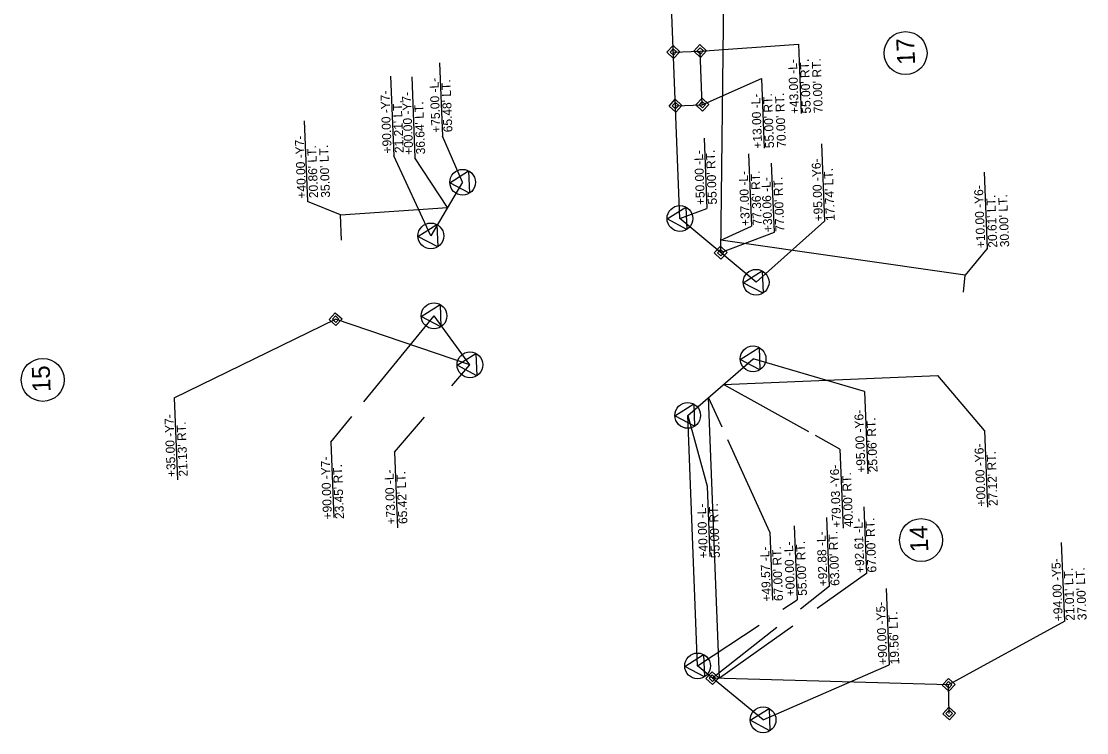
# Model space of a CAD drawing. Extents: x 1627970 to 1628801, y 761752 to 765698.
# Drawn here: x 1628129 to 1628724, y 762940 to 763337 of the extents above; entities that cross this region are included whole.
import ezdxf

# ---------------------------------------------------------------- set-up
doc = ezdxf.new("R2010")
doc.units = 0
for name, color, linetype in [('Exist Other Culture Gas Pump or Vent CELL', 7, 'Continuous'), ('Exist Property Line Leader', 7, 'Continuous'), ('Exist Property Line Text', 7, 'Continuous'), ('Exist Property Owner Number CELL', 7, 'Continuous'), ('Exist Right of Way Control of Access Line', 7, 'Continuous'), ('Exist Right of Way Monument Leader', 7, 'Continuous'), ('Exist Right of Way Monument Text', 7, 'Continuous'), ('Exist Roads EOT', 7, 'Continuous'), ('Exist Utilities Gas UG Line', 7, 'Continuous'), ('Exist Utilities Gas UG Line Text', 7, 'Continuous'), ('Exist Utilities Other Unknown UG SUE Text', 7, 'Continuous')]:
    doc.layers.add(name, color=color, linetype=linetype)

msp = doc.modelspace()

# ---------------------------------------------------------------- linework, layer by layer
at = {"layer": 'Exist Other Culture Gas Pump or Vent CELL'}
for p, q in [((1628508.24, 763320.26), (1628563.07, 763324.14)), ((1628563.07, 763324.14), (1628564.6, 763285.32)), ((1628509.42, 763290.28), (1628542.51, 763304.85)), ((1628542.51, 763304.85), (1628544.04, 763266.03))]:
    msp.add_line(p, q, dxfattribs=at)
at = {"layer": 'Exist Property Line Leader'}
for p, q in [((1628519.69, 763207.68), (1628522.83, 763457.94)), ((1628379.63, 763145.05), (1628304.6, 763170.52)), ((1628646.98, 762966.38), (1628515.04, 762970.13)), ((1628647.3, 762950.39), (1628646.98, 762966.38))]:
    msp.add_line(p, q, dxfattribs=at)
at = {"layer": 'Exist Property Line Text'}
for p, q in [((1628622.91, 763319.11), (1628622.91, 763319.11)), ((1628141.06, 763136.66), (1628141.06, 763136.66)), ((1628631.59, 763047.2), (1628631.59, 763047.2))]:
    msp.add_line(p, q, dxfattribs=at)
for centre in [(1628622.91, 763319.11), (1628141.06, 763136.66), (1628631.59, 763047.2)]:
    msp.add_circle(centre, 12, dxfattribs=at)
at = {"layer": 'Exist Property Owner Number CELL'}
for p, q in [((1628493.25, 763319.67), (1628508.24, 763320.26)), ((1628509.42, 763290.28), (1628508.24, 763320.26)), ((1628494.44, 763289.69), (1628509.42, 763290.28))]:
    msp.add_line(p, q, dxfattribs=at)
at = {"layer": 'Exist Right of Way Control of Access Line'}
for p, q in [((1628496.92, 763226.74), (1628473.87, 763811.28)), ((1628375.55, 763246.97), (1628357.79, 763217.01)), ((1628539.46, 763191.13), (1628496.92, 763226.74)), ((1628379.63, 763145.05), (1628359.56, 763172.38)), ((1628501.25, 763116.82), (1628537.76, 763148.37)), ((1628506.77, 762976.93), (1628501.25, 763116.82)), ((1628543.35, 762946.87), (1628506.77, 762976.93))]:
    msp.add_line(p, q, dxfattribs=at)
at = {"layer": 'Exist Right of Way Monument Leader'}
for points in [[(1628489.66, 763319.52), (1628493.11, 763323.26), (1628496.85, 763319.81), (1628493.4, 763316.07)], [(1628504.65, 763320.11), (1628508.1, 763323.85), (1628511.84, 763320.4), (1628508.38, 763316.66)], [(1628506.44, 763320.19), (1628508.17, 763322.06), (1628510.04, 763320.33), (1628508.31, 763318.46)], [(1628491.46, 763319.59), (1628493.18, 763321.46), (1628495.05, 763319.74), (1628493.32, 763317.87)], [(1628490.84, 763289.55), (1628494.29, 763293.29), (1628498.03, 763289.83), (1628494.58, 763286.09)], [(1628505.83, 763290.14), (1628509.28, 763293.88), (1628513.02, 763290.42), (1628509.57, 763286.68)], [(1628492.64, 763289.62), (1628494.37, 763291.49), (1628496.23, 763289.76), (1628494.51, 763287.89)], [(1628507.63, 763290.21), (1628509.35, 763292.08), (1628511.22, 763290.35), (1628509.5, 763288.48)], [(1628516.09, 763207.54), (1628519.55, 763211.27), (1628523.28, 763207.82), (1628519.83, 763204.08)], [(1628517.89, 763207.61), (1628519.62, 763209.48), (1628521.49, 763207.75), (1628519.76, 763205.88)], [(1628301, 763170.38), (1628304.45, 763174.12), (1628308.19, 763170.66), (1628304.74, 763166.92)], [(1628302.8, 763170.45), (1628304.52, 763172.32), (1628306.39, 763170.59), (1628304.67, 763168.72)], [(1628511.45, 762969.99), (1628514.9, 762973.73), (1628518.64, 762970.27), (1628515.19, 762966.54)], [(1628513.24, 762970.06), (1628514.97, 762971.93), (1628516.84, 762970.2), (1628515.11, 762968.33)], [(1628643.38, 762966.24), (1628646.84, 762969.98), (1628650.57, 762966.52), (1628647.12, 762962.78)], [(1628645.18, 762966.31), (1628646.91, 762968.18), (1628648.78, 762966.45), (1628647.05, 762964.58)], [(1628643.7, 762950.25), (1628647.16, 762953.99), (1628650.89, 762950.53), (1628647.44, 762946.8)], [(1628645.5, 762950.32), (1628647.23, 762952.19), (1628649.09, 762950.46), (1628647.37, 762948.59)]]:
    msp.add_lwpolyline(points, close=True, dxfattribs=at)
at = {"layer": 'Exist Right of Way Monument Text'}
for p, q in [((1628307.28, 763228.8), (1628367.17, 763232.83)), ((1628307.84, 763214.67), (1628307.28, 763228.8)), ((1628656.22, 763195.03), (1628519.77, 763214.63)), ((1628655.35, 763185.64), (1628656.22, 763195.03)), ((1628521.21, 763134.07), (1628640.95, 763139.09)), ((1628519.05, 762970.02), (1628512.87, 763126.86))]:
    msp.add_line(p, q, dxfattribs=at)
at = {"layer": 'Exist Roads EOT'}
for p, q in [((1628549.66, 763219.19), (1628548.09, 763257.67)), ((1628519.69, 763207.68), (1628549.66, 763219.19)), ((1628214.44, 763126.7), (1628304.6, 763170.52)), ((1628214.44, 763126.7), (1628216.26, 763080.77)), ((1628580.45, 763021.49), (1628578.88, 763059.86)), ((1628711.81, 763002), (1628710.01, 763045.88)), ((1628580.45, 763021.49), (1628564.19, 763008.72)), ((1628711.81, 763002), (1628646.98, 762966.38)), ((1628551.04, 762998.4), (1628515.04, 762970.13))]:
    msp.add_line(p, q, dxfattribs=at)
at = {"layer": 'Exist Utilities Gas UG Line'}
for p, q in [((1628362.69, 763313.63), (1628364.3, 763272.66)), ((1628335.31, 763306.19), (1628337.06, 763261.75)), ((1628375.55, 763246.97), (1628364.3, 763272.66)), ((1628510.48, 763271.57), (1628512.03, 763232.29)), ((1628576.03, 763268.36), (1628577.73, 763225.3)), ((1628357.79, 763217.01), (1628337.06, 763261.75)), ((1628496.92, 763226.74), (1628512.03, 763232.29)), ((1628539.46, 763191.13), (1628577.73, 763225.3)), ((1628320.3, 763124.33), (1628359.56, 763172.38)), ((1628369.45, 763133.28), (1628379.63, 763145.05)), ((1628599.97, 763130.08), (1628537.76, 763148.37)), ((1628599.97, 763130.08), (1628601.78, 763084.26)), ((1628301.96, 763101.88), (1628313.68, 763116.23)), ((1628337.51, 763096.3), (1628354.3, 763115.74)), ((1628501.25, 763116.82), (1628512.12, 763077.28)), ((1628301.96, 763101.88), (1628303.62, 763059.82)), ((1628337.51, 763096.3), (1628339.18, 763053.99)), ((1628512.12, 763077.28), (1628513.67, 763038)), ((1628560.69, 763055.23), (1628562.32, 763013.84)), ((1628612.13, 763020.23), (1628613.81, 762977.6)), ((1628554.47, 763008.62), (1628562.32, 763013.84)), ((1628506.77, 762976.93), (1628541.11, 762999.75)), ((1628543.35, 762946.87), (1628613.81, 762977.6))]:
    msp.add_line(p, q, dxfattribs=at)
at = {"layer": 'Exist Utilities Gas UG Line Text'}
for p, q in [((1628347.13, 763305.76), (1628348.91, 763260.62)), ((1628287.13, 763281.24), (1628288.91, 763236.19)), ((1628535.26, 763262.91), (1628536.85, 763222.49)), ((1628367.17, 763232.83), (1628348.91, 763260.62)), ((1628666.86, 763252.64), (1628668.55, 763209.91)), ((1628307.28, 763228.8), (1628288.91, 763236.19)), ((1628519.77, 763214.63), (1628536.85, 763222.49)), ((1628668.55, 763209.91), (1628656.22, 763195.03)), ((1628667.09, 763108.4), (1628640.95, 763139.09)), ((1628568.84, 763107.63), (1628521.21, 763134.07)), ((1628520.43, 763110.29), (1628512.87, 763126.86)), ((1628667.09, 763108.4), (1628668.78, 763065.67)), ((1628547.19, 763051.67), (1628523.71, 763103.1)), ((1628586.31, 763097.94), (1628572.68, 763105.5)), ((1628586.31, 763097.94), (1628588.05, 763053.87)), ((1628599.58, 763065.79), (1628601.05, 763028.51)), ((1628547.19, 763051.67), (1628548.69, 763013.66)), ((1628601.05, 763028.51), (1628573.62, 763008.95)), ((1628559.98, 762999.22), (1628519.05, 762970.02))]:
    msp.add_line(p, q, dxfattribs=at)
at = {"layer": 'Exist Utilities Other Unknown UG SUE Text'}
for p, q in [((1628493.25, 763319.67), (1628493.25, 763319.67)), ((1628508.24, 763320.26), (1628508.24, 763320.26)), ((1628494.44, 763289.69), (1628494.44, 763289.69)), ((1628509.42, 763290.28), (1628509.42, 763290.28)), ((1628375.55, 763246.97), (1628375.55, 763246.97)), ((1628496.92, 763226.74), (1628496.92, 763226.74)), ((1628357.79, 763217.01), (1628357.79, 763217.01)), ((1628519.69, 763207.68), (1628519.69, 763207.68)), ((1628539.46, 763191.13), (1628539.46, 763191.13)), ((1628304.6, 763170.52), (1628304.6, 763170.52)), ((1628359.56, 763172.38), (1628359.56, 763172.38)), ((1628379.63, 763145.05), (1628379.63, 763145.05)), ((1628537.76, 763148.37), (1628537.76, 763148.37)), ((1628501.25, 763116.82), (1628501.25, 763116.82)), ((1628506.77, 762976.93), (1628506.77, 762976.93)), ((1628515.04, 762970.13), (1628515.04, 762970.13)), ((1628646.98, 762966.38), (1628646.98, 762966.38)), ((1628647.3, 762950.39), (1628647.3, 762950.39)), ((1628543.35, 762946.87), (1628543.35, 762946.87))]:
    msp.add_line(p, q, dxfattribs=at)
for points in [[(1628368.34, 763246.7), (1628378.91, 763253.34), (1628379.4, 763240.87)], [(1628489.71, 763226.47), (1628500.28, 763233.11), (1628500.77, 763220.64)], [(1628350.58, 763216.74), (1628361.15, 763223.38), (1628361.64, 763210.91)], [(1628532.25, 763190.86), (1628542.82, 763197.5), (1628543.31, 763185.03)], [(1628352.36, 763172.11), (1628362.92, 763178.75), (1628363.41, 763166.28)], [(1628372.42, 763144.78), (1628382.98, 763151.42), (1628383.47, 763138.95)], [(1628530.56, 763148.1), (1628541.12, 763154.74), (1628541.61, 763142.27)], [(1628494.04, 763116.55), (1628504.61, 763123.19), (1628505.1, 763110.72)], [(1628499.56, 762976.66), (1628510.13, 762983.3), (1628510.62, 762970.83)], [(1628536.14, 762946.6), (1628546.7, 762953.24), (1628547.2, 762940.77)]]:
    msp.add_lwpolyline(points, close=True, dxfattribs=at)
for centre in [(1628375.55, 763246.97), (1628496.92, 763226.74), (1628357.79, 763217.01), (1628539.46, 763191.13), (1628359.56, 763172.38), (1628537.76, 763148.37), (1628379.63, 763145.05), (1628501.25, 763116.82), (1628506.77, 762976.93), (1628543.35, 762946.87)]:
    msp.add_circle(centre, 7.2, dxfattribs=at)

# ---------------------------------------------------------------- texts
at = {"layer": 'Exist Other Culture Gas Pump or Vent CELL'}
for s, p in [('+43.00 -L-', (1628563.43, 763285.15)), ("55.00' RT.", (1628570.09, 763285.41)), ("70.00' RT.", (1628576.75, 763285.68)), ('+13.00 -L-', (1628542.87, 763265.86)), ("55.00' RT.", (1628549.53, 763266.12)), ("70.00' RT.", (1628556.19, 763266.38))]:
    msp.add_text(s, height=5, rotation=92.25819, dxfattribs=at).set_placement(p)
at = {"layer": 'Exist Property Line Text'}
for s, p in [('17', (1628628.29, 763312.79)), ('15', (1628145.45, 763129.97)), ('14', (1628635.67, 763040.62))]:
    msp.add_text(s, height=10, rotation=92.25819, dxfattribs=at).set_placement(p)
at = {"layer": 'Exist Roads EOT'}
for s, p in [('+30.06 -L-', (1628548.6, 763219.2)), ("77.00' RT.", (1628555.27, 763219.47)), ('+35.00 -Y7-', (1628215.35, 763082.52)), ("21.13' RT.", (1628222.01, 763082.78)), ('+92.88 -L-', (1628579.39, 763021.5)), ("63.00' RT.", (1628586.05, 763021.76)), ('+94.00 -Y5-', (1628710.75, 763002.01)), ("21.01' LT.", (1628717.41, 763002.28)), ("37.00' LT.", (1628724.07, 763002.54))]:
    msp.add_text(s, height=5, rotation=92.25819, dxfattribs=at).set_placement(p)
at = {"layer": 'Exist Utilities Gas UG Line'}
for s, p in [('+75.00 -L-', (1628363.2, 763274.72)), ("65.48' LT.", (1628369.86, 763274.99)), ('+90.00 -Y7-', (1628335.98, 763263.16)), ("21.21' LT.", (1628342.64, 763263.43)), ('+50.00 -L-', (1628510.92, 763234.35)), ("55.00' RT.", (1628517.58, 763234.61)), ('+95.00 -Y6-', (1628576.79, 763225.23)), ("17.74' LT.", (1628583.45, 763225.49)), ('+95.00 -Y6-', (1628600.64, 763084.9)), ("25.06' RT.", (1628607.31, 763085.16)), ('+90.00 -Y7-', (1628302.63, 763058.83)), ("23.45' RT.", (1628309.29, 763059.09)), ('+73.00 -L-', (1628338.07, 763056.05)), ("65.42' LT.", (1628344.73, 763056.31)), ('+40.00 -L-', (1628512.6, 763036.99)), ("55.00' RT.", (1628519.26, 763037.25)), ('+00.00 -L-', (1628561.21, 763015.9)), ("55.00' RT.", (1628567.87, 763016.17)), ('+90.00 -Y5-', (1628612.78, 762977.68)), ("19.56' LT.", (1628619.45, 762977.94))]:
    msp.add_text(s, height=5, rotation=92.25819, dxfattribs=at).set_placement(p)
at = {"layer": 'Exist Utilities Gas UG Line Text'}
for s, p in [('+00.00 -Y7-', (1628348, 763262.37)), ("36.64' LT.", (1628354.66, 763262.64)), ('+40.00 -Y7-', (1628288.21, 763237.96)), ("20.86' LT.", (1628294.87, 763238.22)), ("35.00' LT.", (1628301.53, 763238.48)), ('+37.00 -L-', (1628536, 763222.7)), ("77.36' RT.", (1628542.66, 763222.96)), ('+10.00 -Y6-', (1628667.51, 763210.29)), ("20.61' LT.", (1628674.17, 763210.56)), ("30.00' LT.", (1628680.83, 763210.82)), ('+00.00 -Y6-', (1628667.73, 763066.05)), ("27.12' RT.", (1628674.4, 763066.32)), ('+79.03 -Y6-', (1628587, 763054.25)), ("40.00' RT.", (1628593.67, 763054.51)), ('+92.61 -L-', (1628600.01, 763028.9)), ("67.00' RT.", (1628606.67, 763029.16)), ('+49.57 -L-', (1628547.87, 763012.98)), ("67.00' RT.", (1628554.54, 763013.24))]:
    msp.add_text(s, height=5, rotation=92.25819, dxfattribs=at).set_placement(p)

doc.saveas('drawing.dxf')
